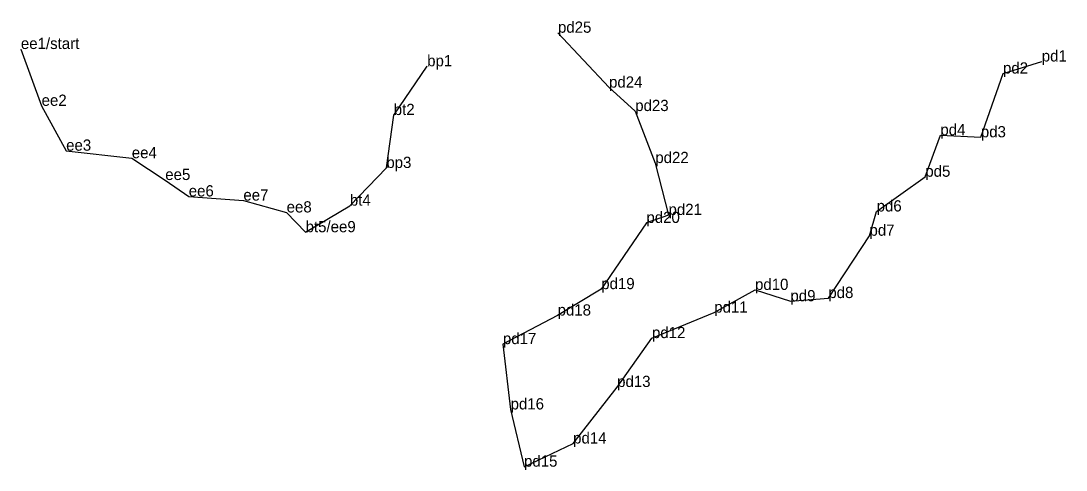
# Model space of a CAD drawing. Extents: x 2072529 to 2267990, y 436423 to 470008.
# Drawn here: x 2229650 to 2230209, y 438830 to 439070 of the extents above; entities that cross this region are included whole.
import ezdxf

# ---------------------------------------------------------------- set-up
doc = ezdxf.new("R2010")
doc.units = 0
doc.layers.add('Level 3', color=7, linetype='Continuous')
doc.layers.add('Old_Level_52', color=7, linetype='Continuous')

msp = doc.modelspace()

# ---------------------------------------------------------------- linework, layer by layer
at = {"layer": 'Level 3'}
for p, q in [((2229937.356, 439063.633), (2229937.356, 439063.633)), ((2229650.379, 439054.943), (2229650.379, 439054.943)), ((2230195.87, 439048.273), (2230195.87, 439048.273)), ((2229867.46, 439045.712), (2229867.46, 439045.712)), ((2230175.151, 439041.829), (2230175.151, 439041.829)), ((2229964.656, 439034.32), (2229964.656, 439034.32)), ((2229661.464, 439024.593), (2229661.464, 439024.593)), ((2229978.63, 439021.803), (2229978.63, 439021.803)), ((2229849.605, 439019.678), (2229849.605, 439019.678)), ((2230141.691, 439008.87), (2230141.691, 439008.87)), ((2230163.317, 439007.777), (2230163.317, 439007.777)), ((2229674.561, 439000.625), (2229674.561, 439000.625)), ((2229709.638, 438996.629), (2229709.638, 438996.629)), ((2229989.358, 438994.03), (2229989.358, 438994.03)), ((2229845.645, 438991.397), (2229845.645, 438991.397)), ((2230133.629, 438986.718), (2230133.629, 438986.718)), ((2229727.521, 438984.968), (2229727.521, 438984.968)), ((2229740.059, 438976.187), (2229740.059, 438976.187)), ((2229769.266, 438974.005), (2229769.266, 438974.005)), ((2229826.148, 438971.265), (2229826.148, 438971.265)), ((2229792.382, 438967.637), (2229792.382, 438967.637)), ((2229996.426, 438966.28), (2229996.426, 438966.28)), ((2230107.636, 438968.161), (2230107.636, 438968.161)), ((2229984.627, 438962.033), (2229984.627, 438962.033)), ((2229802.507, 438957.08), (2229802.507, 438957.08)), ((2230103.807, 438955.209), (2230103.807, 438955.209)), ((2229960.471, 438926.676), (2229960.471, 438926.676)), ((2230042.649, 438926.266), (2230042.649, 438926.266)), ((2230061.569, 438920.202), (2230061.569, 438920.202)), ((2230081.824, 438921.916), (2230081.824, 438921.916)), ((2230020.861, 438914.134), (2230020.861, 438914.134)), ((2229937.16, 438912.593), (2229937.16, 438912.593)), ((2229987.589, 438900.517), (2229987.589, 438900.517)), ((2229907.938, 438897.314), (2229907.938, 438897.314)), ((2229968.973, 438874.416), (2229968.973, 438874.416)), ((2229912.039, 438862.433), (2229912.039, 438862.433)), ((2229945.459, 438844.229), (2229945.459, 438844.229)), ((2229919.236, 438831.853), (2229919.236, 438831.853))]:
    msp.add_line(p, q, dxfattribs=at)
at = {"layer": 'Old_Level_52'}
for points in [[(2229937.356, 439063.633), (2229964.656, 439034.32), (2229978.63, 439021.803), (2229989.358, 438994.03), (2229996.426, 438966.28), (2229984.627, 438962.033), (2229960.471, 438926.676), (2229937.16, 438912.593), (2229907.938, 438897.314), (2229912.039, 438862.433), (2229919.236, 438831.853), (2229945.459, 438844.229), (2229968.973, 438874.416), (2229987.589, 438900.517), (2230020.861, 438914.134), (2230042.649, 438926.266), (2230061.569, 438920.202), (2230081.824, 438921.916), (2230103.807, 438955.209), (2230107.636, 438968.161), (2230133.629, 438986.718), (2230141.691, 439008.87), (2230163.317, 439007.777), (2230175.151, 439041.829), (2230195.87, 439048.273)], [(2229650.379, 439054.943), (2229661.464, 439024.593), (2229674.561, 439000.625), (2229709.638, 438996.629), (2229727.521, 438984.968), (2229740.059, 438976.187), (2229769.266, 438974.005), (2229792.382, 438967.637), (2229802.507, 438957.08), (2229826.148, 438971.265), (2229845.645, 438991.397), (2229849.605, 439019.678), (2229867.46, 439045.712)]]:
    msp.add_lwpolyline(points, dxfattribs=at)

# ---------------------------------------------------------------- texts
for s, p in [('pd25', (2229937.356, 439063.633)), ('ee1/start', (2229650.379, 439054.943)), ('pd1', (2230195.87, 439048.273)), ('bp1', (2229867.46, 439045.712)), ('pd2', (2230175.151, 439041.829)), ('pd24', (2229964.656, 439034.32)), ('ee2', (2229661.464, 439024.593)), ('bt2', (2229849.605, 439019.678)), ('pd23', (2229978.63, 439021.803)), ('pd4', (2230141.691, 439008.87)), ('pd3', (2230163.317, 439007.777)), ('ee3', (2229674.561, 439000.625)), ('ee4', (2229709.638, 438996.629)), ('pd22', (2229989.358, 438994.03)), ('bp3', (2229845.645, 438991.397)), ('pd5', (2230133.629, 438986.718)), ('ee5', (2229727.521, 438984.968)), ('ee6', (2229740.059, 438976.187)), ('ee7', (2229769.266, 438974.005)), ('bt4', (2229826.148, 438971.265)), ('ee8', (2229792.382, 438967.637)), ('pd21', (2229996.426, 438966.28)), ('pd6', (2230107.636, 438968.161)), ('pd20', (2229984.627, 438962.033)), ('bt5/ee9', (2229802.507, 438957.08)), ('pd7', (2230103.807, 438955.209)), ('pd19', (2229960.471, 438926.676)), ('pd10', (2230042.649, 438926.266)), ('pd9', (2230061.569, 438920.202)), ('pd8', (2230081.824, 438921.916)), ('pd11', (2230020.861, 438914.134)), ('pd18', (2229937.16, 438912.593)), ('pd17', (2229907.938, 438897.314)), ('pd12', (2229987.589, 438900.517)), ('pd13', (2229968.973, 438874.416)), ('pd16', (2229912.039, 438862.433)), ('pd14', (2229945.459, 438844.229)), ('pd15', (2229919.236, 438831.853))]:
    msp.add_text(s, height=6).set_placement(p)

doc.saveas('drawing.dxf')
